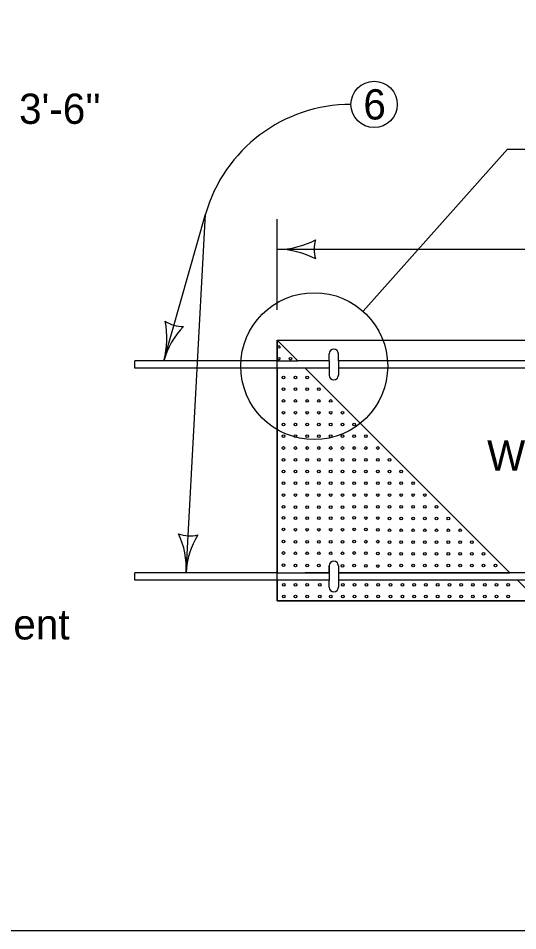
# Model space of a CAD drawing. Extents: x 228 to 3572, y -1307 to 1277.
# Drawn here: x 1691.1 to 1955.3, y -1020 to -537.2 of the extents above; entities that cross this region are included whole.
import ezdxf

# ---------------------------------------------------------------- set-up
doc = ezdxf.new("R2010")
doc.units = 0
for name, color, linetype in [('dsnStdBorder', 7, 'Continuous'), ('dsnStdDimension', 7, 'Continuous'), ('Level 2', 7, 'Continuous'), ('Level 3', 7, 'Continuous')]:
    doc.layers.add(name, color=color, linetype=linetype)

msp = doc.modelspace()

# ---------------------------------------------------------------- linework, layer by layer
at = {"layer": 'dsnStdBorder'}
msp.add_lwpolyline([(332.48, 990.01), (3467.48, 990.01), (3467.48, -1019.99), (332.48, -1019.99)], close=True, dxfattribs=at)
at = {"layer": 'dsnStdDimension'}
for p, q in [((1873.49, -692.22), (1949.92, -606.46)), ((1949.92, -606.46), (1995.05, -606.46)), ((1768.11, -718.36), (1790.12, -640.87)), ((1779.89, -830.56), (1790.12, -640.87)), ((1827.99, -691.46), (1827.99, -643.46)), ((2559.99, -659.46), (1827.99, -659.46))]:
    msp.add_line(p, q, dxfattribs=at)
msp.add_circle((1847.64, -721.23), 38.85, dxfattribs=at)
for centre, radius, start, end in [((1867.08, -662.73), 80, 90, 164.1406), ((1827.99, -616.28), 43.18, 270, 298.0725), ((1864.2, -659.46), 16.68, 162.2666, 197.7334), ((1827.99, -702.64), 43.18, 61.9275, 90), ((1726.57, -706.56), 43.18, 344.1398, 12.2123), ((1778, -683.53), 16.68, 236.4065, 271.8732), ((1809.64, -730.16), 43.18, 136.0673, 164.1398), ((1781.84, -794.4), 16.68, 249.1802, 284.6469), ((1736.78, -828.23), 43.18, 356.9135, 24.986), ((1823.01, -832.88), 43.18, 148.841, 176.9135)]:
    msp.add_arc(centre, radius, start, end, dxfattribs=at)
at = {"layer": 'Level 2'}
for p, q in [((1827.99, -707.46), (1827.99, -715.65)), ((1827.99, -707.46), (1827.99, -718.36)), ((1838.89, -718.36), (1827.99, -707.46)), ((1827.99, -707.46), (1827.99, -718.36)), ((1827.99, -718.36), (1752.79, -718.36)), ((1752.79, -722.36), (1752.79, -718.36)), ((1827.99, -718.36), (1838.89, -718.36)), ((1855.59, -718.36), (1838.89, -718.36)), ((1855.59, -718.36), (1855.59, -714.66)), ((1855.59, -718.36), (1855.59, -722.36)), ((1860.39, -718.36), (1860.39, -714.66)), ((1860.39, -718.36), (1860.39, -722.36)), ((1966.17, -718.36), (1860.39, -718.36)), ((1827.99, -722.36), (1752.79, -722.36)), ((1842.89, -722.36), (1827.99, -722.36)), ((1827.99, -722.36), (1827.99, -830.56)), ((1855.59, -722.36), (1838.89, -722.36)), ((1951.09, -830.56), (1842.89, -722.36)), ((1855.59, -722.36), (1855.59, -726.06)), ((2078.37, -722.36), (1860.39, -722.36)), ((1860.39, -722.36), (1860.39, -726.06)), ((1855.59, -826.86), (1855.59, -830.56)), ((1855.59, -830.56), (1855.59, -826.86)), ((1860.39, -826.86), (1860.39, -830.56)), ((1860.39, -826.86), (1860.39, -830.56)), ((1827.99, -830.56), (1752.79, -830.56)), ((1752.79, -834.56), (1752.79, -830.56)), ((1827.99, -834.56), (1752.79, -834.56)), ((1827.99, -830.56), (1855.59, -830.56)), ((1855.59, -834.56), (1827.99, -834.56)), ((1827.99, -845.46), (1827.99, -834.56)), ((1855.59, -834.56), (1827.99, -834.56)), ((1827.99, -834.56), (1827.99, -845.46)), ((1855.59, -830.56), (1842.89, -830.56)), ((1855.59, -830.56), (1855.59, -834.56)), ((1855.59, -838.26), (1855.59, -834.56)), ((2078.37, -830.56), (1860.39, -830.56)), ((1860.39, -830.56), (1860.39, -834.56)), ((1860.39, -830.56), (1951.09, -830.56)), ((2082.37, -834.56), (1860.39, -834.56)), ((1955.09, -834.56), (1860.39, -834.56)), ((1860.39, -834.56), (1860.39, -838.26)), ((1965.99, -845.46), (1955.09, -834.56)), ((1827.99, -845.46), (1955.27, -845.46)), ((1951.71, -845.46), (1827.99, -845.46)), ((1827.99, -845.46), (1965.99, -845.46))]:
    msp.add_line(p, q, dxfattribs=at)
msp.add_lwpolyline([(1827.99, -707.46), (2559.99, -707.46), (2559.99, -845.46), (1827.99, -845.46)], close=True, dxfattribs=at)
for centre, radius in [((1879.33, -582.73), 12.25), ((1828.85, -711.09), 0.711), ((1828.85, -717.31), 0.711), ((1835.07, -717.31), 0.711), ((1831.44, -727.21), 0.711), ((1837.66, -727.21), 0.711), ((1843.89, -727.21), 0.711), ((1831.44, -733.43), 0.711), ((1837.66, -733.43), 0.711), ((1843.89, -733.43), 0.711), ((1850.11, -733.43), 0.711), ((1831.44, -739.66), 0.711), ((1837.66, -739.66), 0.711), ((1843.89, -739.66), 0.711), ((1850.11, -739.66), 0.711), ((1856.33, -739.66), 0.711), ((1831.44, -745.88), 0.711), ((1837.66, -745.88), 0.711), ((1843.89, -745.88), 0.711), ((1850.11, -745.88), 0.711), ((1856.33, -745.88), 0.711), ((1862.55, -745.88), 0.711), ((1831.44, -752.1), 0.711), ((1837.66, -752.1), 0.711), ((1843.89, -752.1), 0.711), ((1850.11, -752.1), 0.711), ((1856.33, -752.1), 0.711), ((1862.55, -752.1), 0.711), ((1868.78, -752.1), 0.711), ((1831.44, -758.32), 0.711), ((1837.66, -758.32), 0.711), ((1843.89, -758.32), 0.711), ((1850.11, -758.32), 0.711), ((1856.33, -758.32), 0.711), ((1862.55, -758.32), 0.711), ((1868.78, -758.32), 0.711), ((1875, -758.32), 0.711), ((1831.44, -764.55), 0.711), ((1837.66, -764.55), 0.711), ((1843.89, -764.55), 0.711), ((1850.11, -764.55), 0.711), ((1856.33, -764.55), 0.711), ((1862.55, -764.55), 0.711), ((1868.78, -764.55), 0.711), ((1875, -764.55), 0.711), ((1881.22, -764.55), 0.711), ((1831.44, -770.77), 0.711), ((1837.66, -770.77), 0.711), ((1843.89, -770.77), 0.711), ((1850.11, -770.77), 0.711), ((1856.33, -770.77), 0.711), ((1862.55, -770.77), 0.711), ((1868.78, -770.77), 0.711), ((1875, -770.77), 0.711), ((1881.22, -770.77), 0.711), ((1887.44, -770.77), 0.711), ((1831.44, -776.99), 0.711), ((1837.66, -776.99), 0.711), ((1843.89, -776.99), 0.711), ((1850.11, -776.99), 0.711), ((1856.33, -776.99), 0.711), ((1862.55, -776.99), 0.711), ((1868.78, -776.99), 0.711), ((1875, -776.99), 0.711), ((1881.22, -776.99), 0.711), ((1887.44, -776.99), 0.711), ((1893.67, -776.99), 0.711), ((1831.44, -783.21), 0.711), ((1837.66, -783.21), 0.711), ((1843.89, -783.21), 0.711), ((1850.11, -783.21), 0.711), ((1856.33, -783.21), 0.711), ((1862.55, -783.21), 0.711), ((1868.78, -783.21), 0.711), ((1875, -783.21), 0.711), ((1881.22, -783.21), 0.711), ((1887.44, -783.21), 0.711), ((1893.67, -783.21), 0.711), ((1899.89, -783.21), 0.711), ((1831.44, -789.43), 0.711), ((1837.66, -789.43), 0.711), ((1843.89, -789.43), 0.711), ((1850.11, -789.43), 0.711), ((1856.33, -789.43), 0.711), ((1862.55, -789.43), 0.711), ((1868.78, -789.43), 0.711), ((1875, -789.43), 0.711), ((1881.22, -789.43), 0.711), ((1887.44, -789.43), 0.711), ((1893.67, -789.43), 0.711), ((1899.89, -789.43), 0.711), ((1906.11, -789.43), 0.711), ((1831.44, -795.66), 0.711), ((1837.66, -795.83), 0.711), ((1843.89, -795.83), 0.711), ((1850.11, -795.83), 0.711), ((1856.33, -795.83), 0.711), ((1862.55, -795.83), 0.711), ((1868.78, -795.66), 0.711), ((1875, -795.66), 0.711), ((1881.22, -795.66), 0.711), ((1887.44, -795.66), 0.711), ((1893.67, -795.66), 0.711), ((1899.89, -795.66), 0.711), ((1906.11, -795.66), 0.711), ((1912.33, -795.66), 0.711), ((1831.44, -801.49), 0.711), ((1837.66, -801.66), 0.711), ((1843.89, -801.66), 0.711), ((1850.11, -801.66), 0.711), ((1856.33, -801.66), 0.711), ((1862.55, -801.66), 0.711), ((1868.78, -801.49), 0.711), ((1875, -801.6), 0.711), ((1881.22, -801.6), 0.711), ((1887.44, -801.88), 0.711), ((1893.67, -801.88), 0.711), ((1899.89, -801.88), 0.711), ((1906.11, -801.88), 0.711), ((1912.33, -801.88), 0.711), ((1918.56, -801.88), 0.711), ((1831.44, -807.61), 0.711), ((1837.66, -807.78), 0.711), ((1843.89, -807.78), 0.711), ((1850.11, -807.78), 0.711), ((1856.33, -807.78), 0.711), ((1862.55, -807.78), 0.711), ((1868.78, -807.61), 0.711), ((1875, -807.72), 0.711), ((1881.22, -807.82), 0.711), ((1887.44, -808.1), 0.711), ((1893.67, -808.1), 0.711), ((1899.89, -808.1), 0.711), ((1906.11, -808.1), 0.711), ((1912.33, -808.1), 0.711), ((1918.56, -808.1), 0.711), ((1924.78, -808.1), 0.711), ((1831.44, -814), 0.711), ((1837.66, -814.17), 0.711), ((1843.89, -814.17), 0.711), ((1850.11, -814.17), 0.711), ((1856.33, -814.17), 0.711), ((1862.55, -814.17), 0.711), ((1868.78, -814), 0.711), ((1875, -814.11), 0.711), ((1881.22, -814.11), 0.711), ((1887.44, -814.32), 0.711), ((1893.67, -814.32), 0.711), ((1899.89, -814.32), 0.711), ((1906.11, -814.32), 0.711), ((1912.33, -814.32), 0.711), ((1918.56, -814.32), 0.711), ((1924.78, -814.32), 0.711), ((1931, -814.32), 0.711), ((1831.44, -820.11), 0.711), ((1837.66, -820.28), 0.711), ((1843.89, -820.28), 0.711), ((1850.11, -820.28), 0.711), ((1856.33, -820.28), 0.711), ((1862.55, -820.28), 0.711), ((1868.78, -820.11), 0.711), ((1875, -820.22), 0.711), ((1881.22, -820.33), 0.711), ((1887.44, -820.55), 0.711), ((1893.67, -820.55), 0.711), ((1899.89, -820.55), 0.711), ((1906.11, -820.55), 0.711), ((1912.33, -820.55), 0.711), ((1918.56, -820.55), 0.711), ((1924.78, -820.55), 0.711), ((1931, -820.55), 0.711), ((1937.22, -820.55), 0.711), ((1831.44, -826.51), 0.711), ((1837.66, -826.68), 0.711), ((1843.89, -826.68), 0.711), ((1850.11, -826.68), 0.711), ((1862.55, -826.95), 0.711), ((1868.78, -826.78), 0.711), ((1875, -826.89), 0.711), ((1881.22, -827), 0.711), ((1887.44, -826.77), 0.711), ((1893.67, -826.77), 0.711), ((1899.89, -826.77), 0.711), ((1906.11, -826.77), 0.711), ((1912.33, -826.77), 0.711), ((1918.56, -826.77), 0.711), ((1924.78, -826.77), 0.711), ((1931, -826.77), 0.711), ((1937.22, -826.77), 0.711), ((1943.45, -826.77), 0.711), ((1831.48, -836.94), 0.711), ((1837.7, -836.94), 0.711), ((1843.92, -836.94), 0.711), ((1850.53, -836.94), 0.711), ((1862.76, -836.94), 0.711), ((1868.98, -836.94), 0.711), ((1875.2, -836.94), 0.711), ((1881.42, -836.94), 0.711), ((1888.03, -836.94), 0.711), ((1894.25, -836.94), 0.711), ((1900.48, -836.94), 0.711), ((1906.7, -836.94), 0.711), ((1912.92, -836.94), 0.711), ((1919.14, -836.94), 0.711), ((1925.37, -836.94), 0.711), ((1931.59, -836.94), 0.711), ((1937.81, -836.94), 0.711), ((1944.03, -836.94), 0.711), ((1950.26, -836.94), 0.711), ((1831.48, -843.17), 0.711), ((1837.7, -843.17), 0.711), ((1843.92, -843.17), 0.711), ((1850.53, -843.17), 0.711), ((1856.34, -843.17), 0.711), ((1862.76, -843.17), 0.711), ((1868.98, -843.17), 0.711), ((1875.2, -843.17), 0.711), ((1881.42, -843.17), 0.711), ((1888.03, -843.17), 0.711), ((1894.25, -843.17), 0.711), ((1900.48, -843.17), 0.711), ((1906.7, -843.17), 0.711), ((1912.92, -843.17), 0.711), ((1919.14, -843.17), 0.711), ((1925.37, -843.17), 0.711), ((1931.59, -843.17), 0.711), ((1937.81, -843.17), 0.711), ((1944.03, -843.17), 0.711), ((1950.26, -843.17), 0.711)]:
    msp.add_circle(centre, radius, dxfattribs=at)
for centre, start, end in [((1857.99, -714.66), 0, 180), ((1857.99, -726.06), 180, 0), ((1857.99, -826.86), 0, 180), ((1857.99, -838.26), 180, 0)]:
    msp.add_arc(centre, 2.4, start, end, dxfattribs=at)

# ---------------------------------------------------------------- texts
at = {"layer": 'dsnStdDimension'}
for s, p in [("3'-6''", (1691.54, -593.04)), ('Embedment', (1602.88, -865.87))]:
    msp.add_text(s, height=16, dxfattribs=at).set_placement(p)
at = {"layer": 'Level 2'}
msp.add_text('6', height=16, dxfattribs=at).set_placement((1873.62, -590.73))
at = {"layer": 'Level 3'}
msp.add_text('White', height=16, dxfattribs=at).set_placement((1939.06, -776.49))

doc.saveas('drawing.dxf')
